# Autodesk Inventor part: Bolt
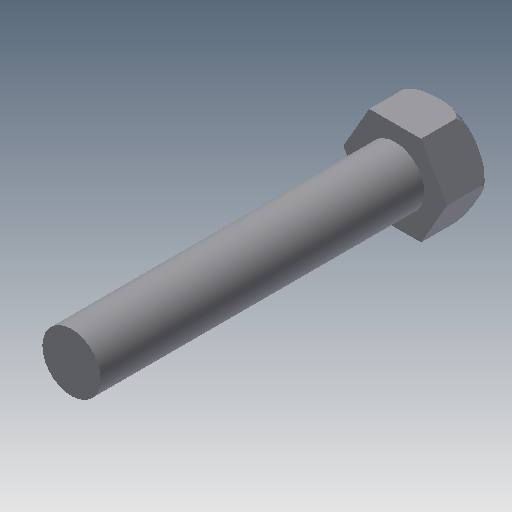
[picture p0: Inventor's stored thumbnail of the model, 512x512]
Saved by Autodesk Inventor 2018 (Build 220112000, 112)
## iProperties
Shininess: 77.0
Length Units: 11269
Angle Units: 11279
Time Units: 11290
Mass Units: 11283
Length Display Precision: 3
Angle Display Precision: 2
Created: 2002-02
Part Number: Bolt
Document SubType Name: Modeling
Designer: ***
Density: 1 g/cm^3
Material: Generic
Appearance: Default
Density: 0.0
Volumn: 0.0
Area: 0.0
PropertySet Name: Model Information
Control State: 0
Master: False
Checked Out: False
Author: ***
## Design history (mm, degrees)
sketch "Sketch1"
  geometry: C1 r 4 at (0, 0)
  constraints: 1 centre point
  dimensions: "d0" = 8 diameter of C1
extrude "Extrusion1" new body sketch "Sketch1" stored distance "d1" = 3.5; taper "d2" = 0 deg
fillet "Fillet1" dims "d3" = 1
sketch "Sketch2"
  geometry: L1 (4, 0)-(2, -3.464); L2 (2, -3.464)-(-2, -3.464); L3 (-2, -3.464)-(-4, 0); L4 (-4, 0)-(-2, 3.464); L5 (-2, 3.464)-(2, 3.464); L6 (2, 3.464)-(4, 0); 2 further points
  constraints: 12 end point, 1 coincident, 11 other
extrude "Extrusion2" sketch "Sketch2" extent not by distance; stored distance "d4" = 3.5; taper "d5" = 0 deg
sketch "Sketch3"
  geometry: C1 r 2.25 at (0, 0)
  constraints: 1 centre point
  dimensions: "d6" = 4.5 diameter of C1
extrude "Extrusion3" join sketch "Sketch3" distance "d7" = 25; taper "d8" = 0 deg
body "Solid1"
